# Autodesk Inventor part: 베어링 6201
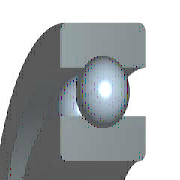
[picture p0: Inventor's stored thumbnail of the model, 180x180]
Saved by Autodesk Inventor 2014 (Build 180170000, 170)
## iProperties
Created: 2015-12
Part Number: 베어링 6201
Material: 강철, 연강
Description: 깊은 그루브 볼 베어링
Document SubType Name: Modeling
Standard: KS B 2023
Designer: mdu
Standards Organization: KS
Language: ko-KR
Size Designation: 6201 - 12 x 32 x 10
Categories: <MemberInstance><Categories><Category DisplayName="샤프트 부품" InternalName="7f7aeb1f-a693-4053-b835-cee3144e0d98" Mnemonic="SHFT"><Category DisplayName="베어링" Inter
Density: 7.86 g/cm^3
Mass: 36.8026 g
Surface Area: 42.5728 cm^2
Volume: 4.68226 cm^3
Appearance: 밝은 황색
Company: 한국ATC센터
IsCustomPart: 1
Author: mdu
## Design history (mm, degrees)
sketch "스케치" dims "d0" = 5.2 (= -0.26 x WD + 0.26 x BD)
  geometry: L1 (2.4, 11)-(7.6, 11); L2 (5, 11)-(5, 8.4); L3 (5, 11)-(5, 13.6); L4 (3.068, 9.26)-(0, 9.26); L5 (0, 6)-(10, 6); L6 (3.068, 12.74)-(0, 12.74); L7 (0, 16)-(10, 16); L8 (10, 6)-(10, 9.26); L9 (6.932, 9.26)-(10, 9.26); L10 (6.932, 12.74)-(10, 12.74); L11 (10, 16)-(10, 12.74); L12 (-1.4, 0)-(8.4, 0) reference; L13 (0, -0.3)-(0, 5.3) reference
  constraints: 22 end point, 4 point on line, 2 collinear, 2 perpendicular, 2 symmetric about line, 1 midpoint, 1 parallel, 14 other
  dimensions: "d9" = 12 diameter of L5 L12 (= WD); "d11" = 32 diameter of L7 L12 (= BD); "d12" = 10 distance between parallel lines of L8 L13 (= KB); "d13" = 18.52 diameter of L9 L12 (= 0.326 x BD + 0.674 x WD)
revolve "본체" stored, may be unused: angle "d6" = 90 deg
revolve "볼" stored, may be unused: angle "d7" = 90 deg
pattern_circular "IDS_ARRAYBALL[SIMPL:T]" dims angle "d3" = 360 deg
body "Solid1"
fillet "모깎기1" dims "d1" = 0.6 (= KRS)
other parameters: "WD" = 12 [user parameter; used in 5 equation terms], "BD" = 32 [user parameter; used in 5 equation terms], "KB" = 10 [user parameter; used in 1 equation term], "KRS" = 0.6 [user parameter; used in 1 equation term], "d4" = 0, "d5" = 0, "d8" = 0, "d14" = 0, "d15" = 0, "BBA" = 0 [user parameter], "BC0" = 3100000 [user parameter], "BC" = 6890000 [user parameter], "BR" = 16 (= 0.5 x BD) [user parameter], "WR" = 6 (= 0.5 x WD) [user parameter]
